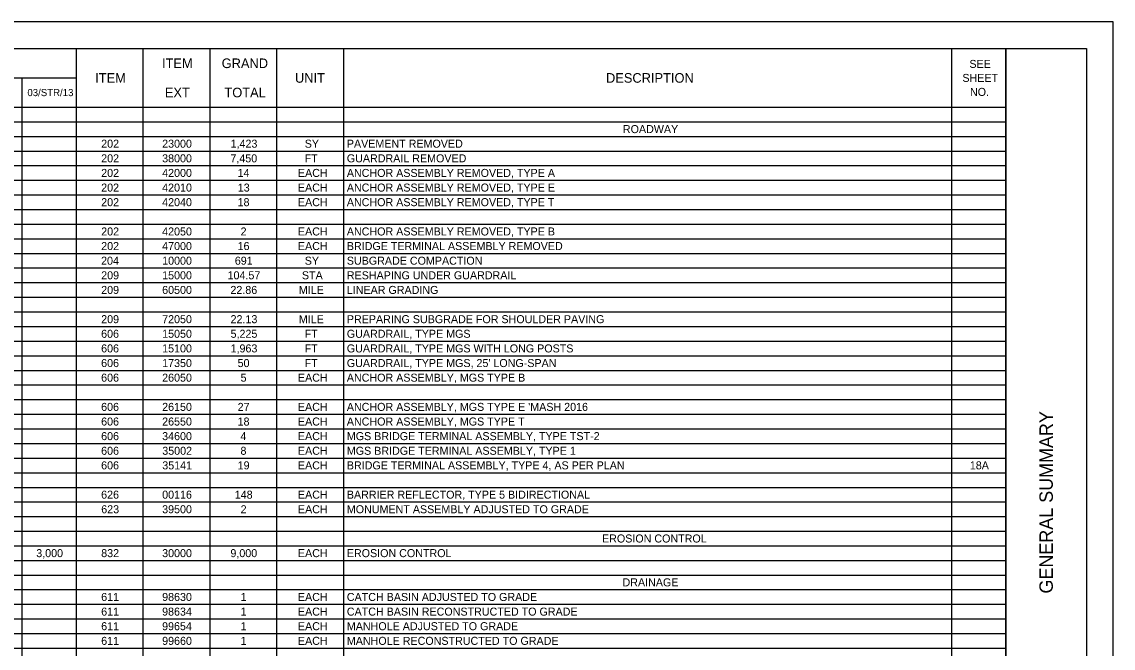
# Model space of a CAD drawing. Extents: x 0 to 34, y 0 to 22.
# Drawn here: x 13.65 to 34, y 10.33 to 22 of the extents above; entities that cross this region are included whole.
import ezdxf

# ---------------------------------------------------------------- set-up
doc = ezdxf.new("R2010")
doc.units = 0
for name, color, linetype in [('Default', 7, 'Continuous'), ('SH_Border', 7, 'Continuous'), ('SH_Cut_Line', 7, 'Continuous'), ('SH_Data', 7, 'Continuous')]:
    doc.layers.add(name, color=color, linetype=linetype)

msp = doc.modelspace()

# ---------------------------------------------------------------- linework, layer by layer
at = {"layer": 'Default'}
for p, q in [((12.636, 21.5), (13.648, 21.5)), ((13.648, 21.5), (32, 21.5)), ((14.66, 21.5), (14.66, 21.227)), ((15.906, 21.5), (15.906, 21.227)), ((17.152, 21.5), (17.152, 21.227)), ((18.398, 21.5), (18.398, 21.227)), ((19.644, 21.5), (19.644, 21.227)), ((30.988, 21.5), (30.988, 21.227)), ((32, 21.5), (32, 21.227)), ((14.66, 21.227), (14.66, 20.955)), ((15.906, 21.227), (15.906, 20.955)), ((17.152, 21.227), (17.152, 20.955)), ((18.398, 21.227), (18.398, 20.955)), ((19.644, 21.227), (19.644, 20.955)), ((30.988, 21.227), (30.988, 20.955)), ((32, 21.227), (32, 20.955)), ((12.636, 20.955), (13.648, 20.955)), ((13.648, 20.955), (14.66, 20.955)), ((13.648, 20.955), (13.648, 20.682)), ((14.66, 20.955), (14.66, 20.682)), ((15.906, 20.955), (15.906, 20.682)), ((17.152, 20.955), (17.152, 20.682)), ((18.398, 20.955), (18.398, 20.682)), ((19.644, 20.955), (19.644, 20.682)), ((30.988, 20.955), (30.988, 20.682)), ((32, 20.955), (32, 20.682)), ((13.648, 20.682), (13.648, 20.41)), ((14.66, 20.682), (14.66, 20.41)), ((15.906, 20.682), (15.906, 20.41)), ((17.152, 20.682), (17.152, 20.41)), ((18.398, 20.682), (18.398, 20.41)), ((19.644, 20.682), (19.644, 20.41)), ((30.988, 20.682), (30.988, 20.41)), ((32, 20.682), (32, 20.41)), ((12.636, 20.41), (13.648, 20.41)), ((13.648, 20.41), (32, 20.41)), ((13.648, 20.41), (13.648, 20.137)), ((14.66, 20.41), (14.66, 20.137)), ((15.906, 20.41), (15.906, 20.137)), ((17.152, 20.41), (17.152, 20.137)), ((18.398, 20.41), (18.398, 20.137)), ((19.644, 20.41), (19.644, 20.137)), ((30.988, 20.41), (30.988, 20.137)), ((32, 20.41), (32, 20.137)), ((12.636, 20.137), (13.648, 20.137)), ((13.648, 20.137), (32, 20.137)), ((13.648, 20.137), (13.648, 18.774)), ((14.66, 20.137), (14.66, 18.774)), ((15.906, 20.137), (15.906, 18.774)), ((17.152, 20.137), (17.152, 18.774)), ((18.398, 20.137), (18.398, 18.774)), ((19.644, 20.137), (19.644, 18.774)), ((30.988, 20.137), (30.988, 18.774)), ((32, 20.137), (32, 18.774)), ((12.636, 19.865), (13.648, 19.865)), ((13.648, 19.865), (32, 19.865)), ((12.636, 19.592), (13.648, 19.592)), ((13.648, 19.592), (32, 19.592)), ((12.636, 19.32), (13.648, 19.32)), ((13.648, 19.32), (32, 19.32)), ((12.636, 19.047), (13.648, 19.047)), ((13.648, 19.047), (32, 19.047)), ((12.636, 18.774), (13.648, 18.774)), ((13.648, 18.774), (32, 18.774)), ((13.648, 18.774), (13.648, 18.229)), ((14.66, 18.774), (14.66, 18.229)), ((15.906, 18.774), (15.906, 18.229)), ((17.152, 18.774), (17.152, 18.229)), ((18.398, 18.774), (18.398, 18.229)), ((19.644, 18.774), (19.644, 18.229)), ((30.988, 18.774), (30.988, 18.229)), ((32, 18.774), (32, 18.229)), ((12.636, 18.502), (13.648, 18.502)), ((13.648, 18.502), (32, 18.502)), ((12.636, 18.229), (13.648, 18.229)), ((13.648, 18.229), (32, 18.229)), ((13.648, 18.229), (13.648, 17.957)), ((14.66, 18.229), (14.66, 17.957)), ((15.906, 18.229), (15.906, 17.957)), ((17.152, 18.229), (17.152, 17.957)), ((18.398, 18.229), (18.398, 17.957)), ((19.644, 18.229), (19.644, 17.957)), ((30.988, 18.229), (30.988, 17.957)), ((32, 18.229), (32, 17.957)), ((12.636, 17.957), (13.648, 17.957)), ((13.648, 17.957), (32, 17.957)), ((13.648, 17.957), (13.648, 17.684)), ((14.66, 17.957), (14.66, 17.684)), ((15.906, 17.957), (15.906, 17.684)), ((17.152, 17.957), (17.152, 17.684)), ((18.398, 17.957), (18.398, 17.684)), ((19.644, 17.957), (19.644, 17.684)), ((30.988, 17.957), (30.988, 17.684)), ((32, 17.957), (32, 17.684)), ((12.636, 17.684), (13.648, 17.684)), ((13.648, 17.684), (32, 17.684)), ((13.648, 17.684), (13.648, 17.412)), ((14.66, 17.684), (14.66, 17.412)), ((15.906, 17.684), (15.906, 17.412)), ((17.152, 17.684), (17.152, 17.412)), ((18.398, 17.684), (18.398, 17.412)), ((19.644, 17.684), (19.644, 17.412)), ((30.988, 17.684), (30.988, 17.412)), ((32, 17.684), (32, 17.412)), ((12.636, 17.412), (13.648, 17.412)), ((13.648, 17.412), (32, 17.412)), ((13.648, 17.412), (13.648, 17.139)), ((14.66, 17.412), (14.66, 17.139)), ((15.906, 17.412), (15.906, 17.139)), ((17.152, 17.412), (17.152, 17.139)), ((18.398, 17.412), (18.398, 17.139)), ((19.644, 17.412), (19.644, 17.139)), ((30.988, 17.412), (30.988, 17.139)), ((32, 17.412), (32, 17.139)), ((12.636, 17.139), (13.648, 17.139)), ((13.648, 17.139), (32, 17.139)), ((13.648, 17.139), (13.648, 16.867)), ((14.66, 17.139), (14.66, 16.867)), ((15.906, 17.139), (15.906, 16.867)), ((17.152, 17.139), (17.152, 16.867)), ((18.398, 17.139), (18.398, 16.867)), ((19.644, 17.139), (19.644, 16.867)), ((30.988, 17.139), (30.988, 16.867)), ((32, 17.139), (32, 16.867)), ((12.636, 16.867), (13.648, 16.867)), ((13.648, 16.867), (32, 16.867)), ((13.648, 16.867), (13.648, 16.321)), ((14.66, 16.867), (14.66, 16.321)), ((15.906, 16.867), (15.906, 16.321)), ((17.152, 16.867), (17.152, 16.321)), ((18.398, 16.867), (18.398, 16.321)), ((19.644, 16.867), (19.644, 16.321)), ((30.988, 16.867), (30.988, 16.321)), ((32, 16.867), (32, 16.321)), ((12.636, 16.594), (13.648, 16.594)), ((13.648, 16.594), (32, 16.594)), ((12.636, 16.321), (13.648, 16.321)), ((13.648, 16.321), (32, 16.321)), ((13.648, 16.321), (13.648, 16.049)), ((14.66, 16.321), (14.66, 16.049)), ((15.906, 16.321), (15.906, 16.049)), ((17.152, 16.321), (17.152, 16.049)), ((18.398, 16.321), (18.398, 16.049)), ((19.644, 16.321), (19.644, 16.049)), ((30.988, 16.321), (30.988, 16.049)), ((32, 16.321), (32, 16.049)), ((12.636, 16.049), (13.648, 16.049)), ((13.648, 16.049), (32, 16.049)), ((13.648, 16.049), (13.648, 15.776)), ((14.66, 16.049), (14.66, 15.776)), ((15.906, 16.049), (15.906, 15.776)), ((17.152, 16.049), (17.152, 15.776)), ((18.398, 16.049), (18.398, 15.776)), ((19.644, 16.049), (19.644, 15.776)), ((30.988, 16.049), (30.988, 15.776)), ((32, 16.049), (32, 15.776)), ((12.636, 15.776), (13.648, 15.776)), ((13.648, 15.776), (32, 15.776)), ((13.648, 15.776), (13.648, 15.504)), ((14.66, 15.776), (14.66, 15.504)), ((15.906, 15.776), (15.906, 15.504)), ((17.152, 15.776), (17.152, 15.504)), ((18.398, 15.776), (18.398, 15.504)), ((19.644, 15.776), (19.644, 15.504)), ((30.988, 15.776), (30.988, 15.504)), ((32, 15.776), (32, 15.504)), ((12.636, 15.504), (13.648, 15.504)), ((13.648, 15.504), (32, 15.504)), ((13.648, 15.504), (13.648, 14.959)), ((14.66, 15.504), (14.66, 14.959)), ((15.906, 15.504), (15.906, 14.959)), ((17.152, 15.504), (17.152, 14.959)), ((18.398, 15.504), (18.398, 14.959)), ((19.644, 15.504), (19.644, 14.959)), ((30.988, 15.504), (30.988, 14.959)), ((32, 15.504), (32, 14.959)), ((12.636, 15.231), (13.648, 15.231)), ((13.648, 15.231), (32, 15.231)), ((12.636, 14.959), (13.648, 14.959)), ((13.648, 14.959), (32, 14.959)), ((13.648, 14.959), (13.648, 14.686)), ((14.66, 14.959), (14.66, 14.686)), ((15.906, 14.959), (15.906, 14.686)), ((17.152, 14.959), (17.152, 14.686)), ((18.398, 14.959), (18.398, 14.686)), ((19.644, 14.959), (19.644, 14.686)), ((30.988, 14.959), (30.988, 14.686)), ((32, 14.959), (32, 14.686)), ((12.636, 14.686), (13.648, 14.686)), ((13.648, 14.686), (32, 14.686)), ((13.648, 14.686), (13.648, 14.414)), ((14.66, 14.686), (14.66, 14.414)), ((15.906, 14.686), (15.906, 14.414)), ((17.152, 14.686), (17.152, 14.414)), ((18.398, 14.686), (18.398, 14.414)), ((19.644, 14.686), (19.644, 14.414)), ((30.988, 14.686), (30.988, 14.414)), ((32, 14.686), (32, 14.414)), ((12.636, 14.414), (13.648, 14.414)), ((13.648, 14.414), (32, 14.414)), ((13.648, 14.414), (13.648, 14.141)), ((14.66, 14.414), (14.66, 14.141)), ((15.906, 14.414), (15.906, 14.141)), ((17.152, 14.414), (17.152, 14.141)), ((18.398, 14.414), (18.398, 14.141)), ((19.644, 14.414), (19.644, 14.141)), ((30.988, 14.414), (30.988, 14.141)), ((32, 14.414), (32, 14.141)), ((12.636, 14.141), (13.648, 14.141)), ((13.648, 14.141), (32, 14.141)), ((13.648, 14.141), (13.648, 11.961)), ((14.66, 14.141), (14.66, 11.961)), ((15.906, 14.141), (15.906, 11.961)), ((17.152, 14.141), (17.152, 11.961)), ((18.398, 14.141), (18.398, 11.961)), ((19.644, 14.141), (19.644, 11.961)), ((30.988, 14.141), (30.988, 11.961)), ((32, 14.141), (32, 11.961)), ((12.636, 13.869), (13.648, 13.869)), ((13.648, 13.869), (32, 13.869)), ((12.636, 13.596), (13.648, 13.596)), ((13.648, 13.596), (32, 13.596)), ((12.636, 13.323), (13.648, 13.323)), ((13.648, 13.323), (32, 13.323)), ((12.636, 13.051), (13.648, 13.051)), ((13.648, 13.051), (32, 13.051)), ((12.636, 12.778), (13.648, 12.778)), ((13.648, 12.778), (32, 12.778)), ((12.636, 12.506), (13.648, 12.506)), ((13.648, 12.506), (32, 12.506)), ((12.636, 12.233), (13.648, 12.233)), ((13.648, 12.233), (32, 12.233)), ((12.636, 11.961), (13.648, 11.961)), ((13.648, 11.961), (32, 11.961)), ((13.648, 11.961), (13.648, 11.688)), ((14.66, 11.961), (14.66, 11.688)), ((15.906, 11.961), (15.906, 11.688)), ((17.152, 11.961), (17.152, 11.688)), ((18.398, 11.961), (18.398, 11.688)), ((19.644, 11.961), (19.644, 11.688)), ((30.988, 11.961), (30.988, 11.688)), ((32, 11.961), (32, 11.688)), ((12.636, 11.688), (13.648, 11.688)), ((13.648, 11.688), (32, 11.688)), ((13.648, 11.688), (13.648, 10.598)), ((14.66, 11.688), (14.66, 10.598)), ((15.906, 11.688), (15.906, 10.598)), ((17.152, 11.688), (17.152, 10.598)), ((18.398, 11.688), (18.398, 10.598)), ((19.644, 11.688), (19.644, 10.598)), ((30.988, 11.688), (30.988, 10.598)), ((32, 11.688), (32, 10.598)), ((12.636, 11.416), (13.648, 11.416)), ((13.648, 11.416), (32, 11.416)), ((12.636, 11.143), (13.648, 11.143)), ((13.648, 11.143), (32, 11.143)), ((12.636, 10.87), (13.648, 10.87)), ((13.648, 10.87), (32, 10.87)), ((12.636, 10.598), (13.648, 10.598)), ((13.648, 10.598), (32, 10.598)), ((13.648, 10.598), (13.648, 10.325)), ((14.66, 10.598), (14.66, 10.325)), ((15.906, 10.598), (15.906, 10.325)), ((17.152, 10.598), (17.152, 10.325)), ((18.398, 10.598), (18.398, 10.325)), ((19.644, 10.598), (19.644, 10.325)), ((30.988, 10.598), (30.988, 10.325)), ((32, 10.598), (32, 10.325)), ((12.636, 10.325), (13.648, 10.325)), ((13.648, 10.325), (32, 10.325)), ((13.648, 10.325), (13.648, 10.053)), ((14.66, 10.325), (14.66, 10.053)), ((15.906, 10.325), (15.906, 10.053)), ((17.152, 10.325), (17.152, 10.053)), ((18.398, 10.325), (18.398, 10.053)), ((19.644, 10.325), (19.644, 10.053)), ((30.988, 10.325), (30.988, 10.053)), ((32, 10.325), (32, 10.053))]:
    msp.add_line(p, q, dxfattribs=at)
at = {"layer": 'SH_Border'}
msp.add_line((32, 0.5), (32, 21.5), dxfattribs=at)
msp.add_lwpolyline([(1.5, 21.5), (33.5, 21.5), (33.5, 0.5), (1.5, 0.5)], close=True, dxfattribs=at)
at = {"layer": 'SH_Cut_Line'}
msp.add_lwpolyline([(0, 0), (34, 0), (34, 22), (0, 22)], close=True, dxfattribs=at)

# ---------------------------------------------------------------- texts
at = {"layer": 'Default'}
for s, height, p in [('ITEM', 0.1791, (16.262, 21.138)), ('GRAND', 0.1791, (17.375, 21.138)), ('SEE ', 0.1493, (31.319, 21.141)), ('ITEM', 0.1791, (15.016, 20.865)), ('UNIT', 0.1791, (18.742, 20.865)), ('DESCRIPTION', 0.17911, (24.542, 20.865)), ('SHEET ', 0.1493, (31.188, 20.88)), ('EXT', 0.1791, (16.315, 20.593)), ('TOTAL', 0.1791, (17.426, 20.593)), ('NO.', 0.1493, (31.33, 20.619)), ('03/STR/13', 0.1343, (13.752, 20.615)), ('ROADWAY', 0.1493, (24.857, 19.926)), ('202', 0.1493, (15.128, 19.654)), ('23000', 0.1493, (16.265, 19.654)), ('1,423', 0.1493, (17.541, 19.654)), ('SY', 0.1493, (18.924, 19.654)), ('PAVEMENT REMOVED', 0.14926, (19.709, 19.654)), ('202', 0.1493, (15.128, 19.381)), ('38000', 0.1493, (16.265, 19.381)), ('7,450', 0.1493, (17.538, 19.381)), ('FT', 0.1493, (18.922, 19.381)), ('GUARDRAIL REMOVED', 0.14926, (19.709, 19.381)), ('202', 0.1493, (15.128, 19.109)), ('42000', 0.1493, (16.265, 19.109)), ('14', 0.1493, (17.671, 19.109)), ('EACH', 0.1493, (18.797, 19.109)), ('ANCHOR ASSEMBLY REMOVED, TYPE A', 0.14926, (19.709, 19.109)), ('202', 0.1493, (15.128, 18.836)), ('42010', 0.1493, (16.265, 18.836)), ('13', 0.1493, (17.675, 18.836)), ('EACH', 0.1493, (18.797, 18.836)), ('ANCHOR ASSEMBLY REMOVED, TYPE E', 0.14926, (19.709, 18.836)), ('202', 0.1493, (15.128, 18.564)), ('42040', 0.1493, (16.265, 18.564)), ('18', 0.1493, (17.672, 18.564)), ('EACH', 0.1493, (18.797, 18.564)), ('ANCHOR ASSEMBLY REMOVED, TYPE T', 0.14926, (19.709, 18.564)), ('202', 0.1493, (15.128, 18.018)), ('42050', 0.1493, (16.265, 18.018)), ('2', 0.149, (17.728, 18.018)), ('EACH', 0.1493, (18.797, 18.018)), ('ANCHOR ASSEMBLY REMOVED, TYPE B', 0.14926, (19.709, 18.018)), ('202', 0.1493, (15.128, 17.746)), ('47000', 0.1493, (16.265, 17.746)), ('16', 0.1493, (17.672, 17.746)), ('EACH', 0.1493, (18.797, 17.746)), ('BRIDGE TERMINAL ASSEMBLY REMOVED', 0.14926, (19.709, 17.746)), ('204', 0.1493, (15.126, 17.473)), ('10000', 0.1493, (16.265, 17.473)), ('691', 0.1493, (17.62, 17.473)), ('SY', 0.1493, (18.924, 17.473)), ('SUBGRADE COMPACTION', 0.14926, (19.709, 17.473)), ('209', 0.1493, (15.128, 17.201)), ('15000', 0.1493, (16.265, 17.201)), ('104.57', 0.1493, (17.485, 17.201)), ('STA', 0.1493, (18.871, 17.201)), ('RESHAPING UNDER GUARDRAIL', 0.14926, (19.709, 17.201)), ('209', 0.1493, (15.128, 16.928)), ('60500', 0.1493, (16.265, 16.928)), ('22.86', 0.1493, (17.538, 16.928)), ('MILE', 0.1493, (18.814, 16.928)), ('LINEAR GRADING', 0.14926, (19.709, 16.928)), ('209', 0.1493, (15.128, 16.383)), ('72050', 0.1493, (16.265, 16.383)), ('22.13', 0.1493, (17.541, 16.383)), ('MILE', 0.1493, (18.814, 16.383)), ('PREPARING SUBGRADE FOR SHOULDER PAVING', 0.14926, (19.709, 16.383)), ('606', 0.1493, (15.127, 16.111)), ('15050', 0.1493, (16.265, 16.111)), ('5,225', 0.1493, (17.541, 16.111)), ('FT', 0.1493, (18.922, 16.111)), ('GUARDRAIL, TYPE MGS', 0.14926, (19.709, 16.111)), ('606', 0.1493, (15.127, 15.838)), ('15100', 0.1493, (16.265, 15.838)), ('1,963', 0.1493, (17.541, 15.838)), ('FT', 0.1493, (18.922, 15.838)), ('GUARDRAIL, TYPE MGS WITH LONG POSTS', 0.14926, (19.709, 15.838)), ('606', 0.1493, (15.127, 15.565)), ('17350', 0.1493, (16.265, 15.565)), ('50', 0.1493, (17.672, 15.565)), ('FT', 0.1493, (18.922, 15.565)), ("GUARDRAIL, TYPE MGS, 25' LONG-SPAN", 0.14926, (19.709, 15.565)), ('606', 0.1493, (15.127, 15.293)), ('26050', 0.1493, (16.265, 15.293)), ('5', 0.149, (17.728, 15.293)), ('EACH', 0.1493, (18.797, 15.293)), ('ANCHOR ASSEMBLY, MGS TYPE B', 0.14926, (19.709, 15.293)), ('606', 0.1493, (15.127, 14.748)), ('26150', 0.1493, (16.265, 14.748)), ('27', 0.1493, (17.673, 14.748)), ('EACH', 0.1493, (18.797, 14.748)), ("ANCHOR ASSEMBLY, MGS TYPE E 'MASH 2016", 0.14926, (19.709, 14.748)), ('606', 0.1493, (15.127, 14.475)), ('26550', 0.1493, (16.265, 14.475)), ('18', 0.1493, (17.672, 14.475)), ('EACH', 0.1493, (18.797, 14.475)), ('ANCHOR ASSEMBLY, MGS TYPE T', 0.14926, (19.709, 14.475)), ('606', 0.1493, (15.127, 14.203)), ('34600', 0.1493, (16.265, 14.203)), ('4', 0.149, (17.725, 14.203)), ('EACH', 0.1493, (18.797, 14.203)), ('MGS BRIDGE TERMINAL ASSEMBLY, TYPE TST-2', 0.14926, (19.709, 14.203)), ('606', 0.1493, (15.127, 13.93)), ('35002', 0.1493, (16.267, 13.93)), ('8', 0.149, (17.726, 13.93)), ('EACH', 0.1493, (18.797, 13.93)), ('MGS BRIDGE TERMINAL ASSEMBLY, TYPE 1', 0.14926, (19.709, 13.93)), ('606', 0.1493, (15.127, 13.658)), ('35141', 0.1493, (16.267, 13.658)), ('19', 0.1493, (17.673, 13.658)), ('EACH', 0.1493, (18.797, 13.658)), ('BRIDGE TERMINAL ASSEMBLY, TYPE 4, AS PER PLAN', 0.14926, (19.709, 13.658)), ('18A', 0.1493, (31.327, 13.658)), ('626', 0.1493, (15.127, 13.112)), ('00116', 0.1493, (16.265, 13.112)), ('148', 0.1493, (17.619, 13.112)), ('EACH', 0.1493, (18.797, 13.112)), ('BARRIER REFLECTOR, TYPE 5 BIDIRECTIONAL', 0.14926, (19.709, 13.112)), ('623', 0.1493, (15.129, 12.84)), ('39500', 0.1493, (16.265, 12.84)), ('2', 0.149, (17.728, 12.84)), ('EACH', 0.1493, (18.797, 12.84)), ('MONUMENT ASSEMBLY ADJUSTED TO GRADE', 0.14926, (19.709, 12.84)), ('EROSION CONTROL', 0.14926, (24.468, 12.295)), ('3,000', 0.1493, (13.917, 12.022)), ('832', 0.1493, (15.128, 12.022)), ('30000', 0.1493, (16.265, 12.022)), ('9,000', 0.1493, (17.538, 12.022)), ('EACH', 0.1493, (18.797, 12.022)), ('EROSION CONTROL', 0.14926, (19.709, 12.022)), ('DRAINAGE', 0.1493, (24.85, 11.477)), ('611', 0.1493, (15.128, 11.205)), ('98630', 0.1493, (16.265, 11.205)), ('1', 0.149, (17.727, 11.205)), ('EACH', 0.1493, (18.797, 11.205)), ('CATCH BASIN ADJUSTED TO GRADE', 0.14926, (19.709, 11.205)), ('611', 0.1493, (15.128, 10.932)), ('98634', 0.1493, (16.264, 10.932)), ('1', 0.149, (17.727, 10.932)), ('EACH', 0.1493, (18.797, 10.932)), ('CATCH BASIN RECONSTRUCTED TO GRADE', 0.14926, (19.709, 10.932)), ('611', 0.1493, (15.128, 10.66)), ('99654', 0.1493, (16.264, 10.66)), ('1', 0.149, (17.727, 10.66)), ('EACH', 0.1493, (18.797, 10.66)), ('MANHOLE ADJUSTED TO GRADE', 0.14926, (19.709, 10.66)), ('611', 0.1493, (15.128, 10.387)), ('99660', 0.1493, (16.265, 10.387)), ('1', 0.149, (17.727, 10.387)), ('EACH', 0.1493, (18.797, 10.387)), ('MANHOLE RECONSTRUCTED TO GRADE', 0.14926, (19.709, 10.387))]:
    msp.add_text(s, height=height, dxfattribs=at).set_placement(p)
at = {"layer": 'SH_Data'}
msp.add_text('GENERAL SUMMARY', height=0.25, rotation=90, dxfattribs=at).set_placement((32.875, 11.344))

doc.saveas('drawing.dxf')
